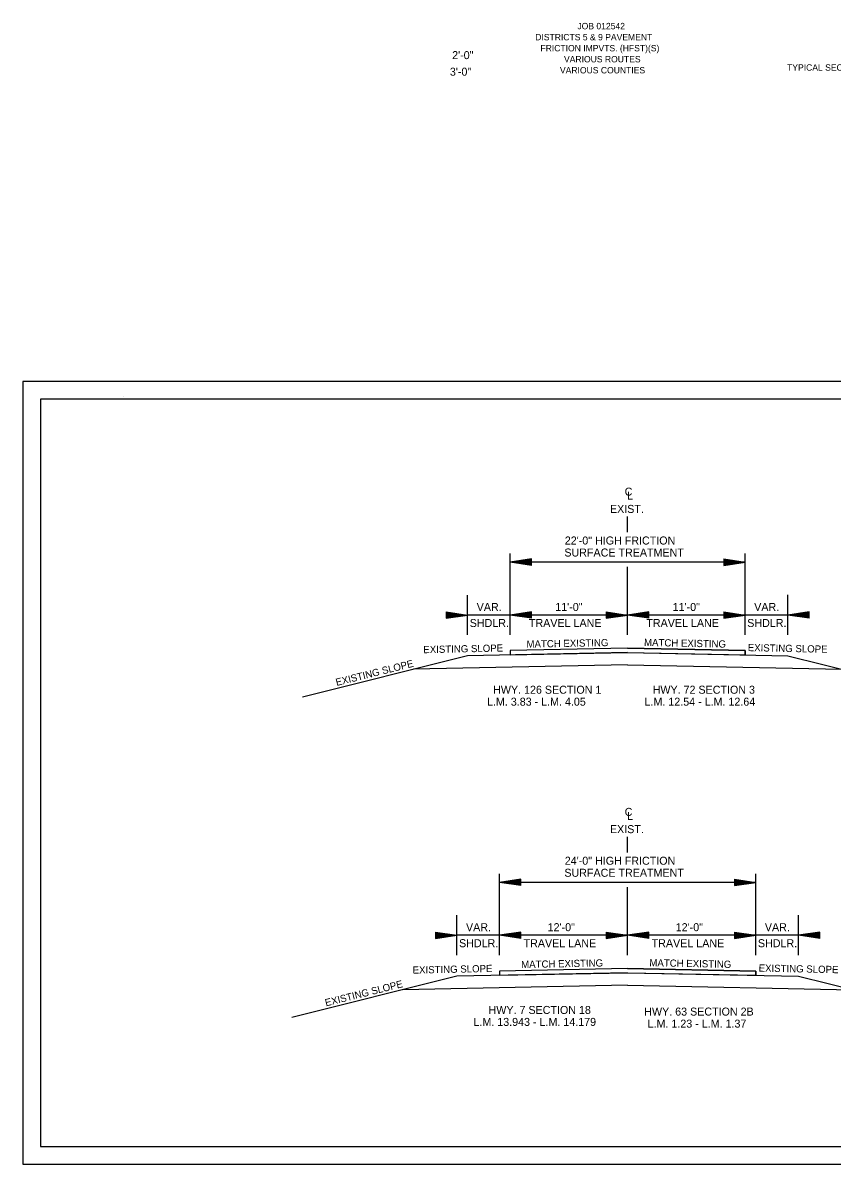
# Model space of a CAD drawing. Extents: x 34757 to 38214, y 51436 to 59430.
# Drawn here: x 34757 to 35894, y 55070 to 56673 of the extents above; entities that cross this region are included whole.
import ezdxf

# ---------------------------------------------------------------- set-up
doc = ezdxf.new("R2010")
doc.units = 0
for name, color, linetype in [('Default', 7, 'Continuous'), ('DSN_DRFT_Junk-No-Plot', 7, 'Continuous'), ('R_Border Notes', 7, 'Continuous'), ('R_Draft', 7, 'Continuous'), ('SHET_Border-Lines', 7, 'Continuous')]:
    doc.layers.add(name, color=color, linetype=linetype)

msp = doc.modelspace()

# ---------------------------------------------------------------- linework, layer by layer
at = {"layer": 'Default'}
for p, q in [((35606.6, 55957.6), (35606.6, 55979.7)), ((35441.6, 55813.4), (35441.6, 55927.7)), ((35771.6, 55813.4), (35771.6, 55927.7)), ((35471.6, 55920.1), (35441.6, 55915.6)), ((35771.6, 55915.6), (35441.6, 55915.6)), ((35471.6, 55911.1), (35441.6, 55915.6)), ((35471.6, 55919.4), (35446.6, 55915.6)), ((35471.6, 55911.9), (35446.6, 55915.6)), ((35471.6, 55918.6), (35451.8, 55915.6)), ((35471.6, 55912.6), (35451.8, 55915.6)), ((35471.6, 55917.8), (35456.8, 55915.6)), ((35471.6, 55913.4), (35456.8, 55915.6)), ((35471.6, 55917.1), (35461.9, 55915.6)), ((35471.6, 55914.1), (35461.9, 55915.6)), ((35471.6, 55916.3), (35466.9, 55915.6)), ((35471.6, 55914.9), (35466.9, 55915.6)), ((35471.6, 55911.1), (35471.6, 55920.1)), ((35741.6, 55920.1), (35771.6, 55915.6)), ((35741.6, 55920.1), (35741.6, 55911.1)), ((35741.6, 55919.4), (35766.6, 55915.6)), ((35741.6, 55918.6), (35761.5, 55915.6)), ((35741.6, 55917.8), (35756.5, 55915.6)), ((35741.6, 55917.1), (35751.4, 55915.6)), ((35741.6, 55916.3), (35746.4, 55915.6)), ((35741.6, 55911.1), (35771.6, 55915.6)), ((35741.6, 55914.1), (35751.4, 55915.6)), ((35741.6, 55912.6), (35761.5, 55915.6)), ((35741.6, 55911.9), (35766.6, 55915.6)), ((35741.6, 55913.4), (35756.5, 55915.6)), ((35741.6, 55914.9), (35746.4, 55915.6)), ((35606.6, 55813.4), (35606.6, 55908.8)), ((35381.6, 55813.4), (35381.6, 55869.3)), ((35831.6, 55813.7), (35831.6, 55869.6)), ((35351.6, 55845.8), (35381.6, 55841.3)), ((35351.6, 55845.8), (35351.6, 55836.8)), ((35351.6, 55845.1), (35376.6, 55841.3)), ((35351.6, 55844.3), (35371.5, 55841.3)), ((35351.6, 55843.6), (35366.5, 55841.3)), ((35351.6, 55842.8), (35361.4, 55841.3)), ((35351.6, 55842), (35356.4, 55841.3)), ((35351.6, 55836.8), (35381.6, 55841.3)), ((35351.6, 55839.9), (35361.4, 55841.3)), ((35351.6, 55838.4), (35371.5, 55841.3)), ((35351.6, 55837.6), (35376.6, 55841.3)), ((35351.6, 55839.1), (35366.5, 55841.3)), ((35351.6, 55840.6), (35356.4, 55841.3)), ((35441.6, 55841.3), (35381.6, 55841.3)), ((35471.6, 55845.8), (35441.6, 55841.3)), ((35606.6, 55841.3), (35441.6, 55841.3)), ((35471.6, 55836.8), (35441.6, 55841.3)), ((35471.6, 55845.1), (35446.6, 55841.3)), ((35471.6, 55837.6), (35446.6, 55841.3)), ((35471.6, 55844.3), (35451.8, 55841.3)), ((35471.6, 55838.4), (35451.8, 55841.3)), ((35471.6, 55843.6), (35456.8, 55841.3)), ((35471.6, 55839.1), (35456.8, 55841.3)), ((35471.6, 55842.8), (35461.9, 55841.3)), ((35471.6, 55839.9), (35461.9, 55841.3)), ((35471.6, 55842), (35466.9, 55841.3)), ((35471.6, 55840.6), (35466.9, 55841.3)), ((35471.6, 55836.8), (35471.6, 55845.8)), ((35576.6, 55845.8), (35606.6, 55841.3)), ((35576.6, 55845.8), (35576.6, 55836.8)), ((35576.6, 55845.1), (35601.6, 55841.3)), ((35576.6, 55844.3), (35596.5, 55841.3)), ((35576.6, 55843.6), (35591.5, 55841.3)), ((35576.6, 55842.8), (35586.4, 55841.3)), ((35576.6, 55842), (35581.4, 55841.3)), ((35576.6, 55836.8), (35606.6, 55841.3)), ((35576.6, 55839.9), (35586.4, 55841.3)), ((35576.6, 55838.4), (35596.5, 55841.3)), ((35576.6, 55837.6), (35601.6, 55841.3)), ((35576.6, 55839.1), (35591.5, 55841.3)), ((35576.6, 55840.6), (35581.4, 55841.3)), ((35636.6, 55845.8), (35606.6, 55841.3)), ((35771.6, 55841.3), (35606.6, 55841.3)), ((35636.6, 55836.8), (35606.6, 55841.3)), ((35636.6, 55845.1), (35611.6, 55841.3)), ((35636.6, 55837.6), (35611.6, 55841.3)), ((35636.6, 55844.3), (35616.8, 55841.3)), ((35636.6, 55838.4), (35616.8, 55841.3)), ((35636.6, 55843.6), (35621.8, 55841.3)), ((35636.6, 55839.1), (35621.8, 55841.3)), ((35636.6, 55842.8), (35626.9, 55841.3)), ((35636.6, 55839.9), (35626.9, 55841.3)), ((35636.6, 55842), (35631.9, 55841.3)), ((35636.6, 55840.6), (35631.9, 55841.3)), ((35636.6, 55836.8), (35636.6, 55845.8)), ((35741.6, 55845.8), (35771.6, 55841.3)), ((35741.6, 55845.8), (35741.6, 55836.8)), ((35741.6, 55845.1), (35766.6, 55841.3)), ((35741.6, 55844.3), (35761.5, 55841.3)), ((35741.6, 55843.6), (35756.5, 55841.3)), ((35741.6, 55842.8), (35751.4, 55841.3)), ((35741.6, 55842), (35746.4, 55841.3)), ((35741.6, 55836.8), (35771.6, 55841.3)), ((35741.6, 55839.9), (35751.4, 55841.3)), ((35741.6, 55838.4), (35761.5, 55841.3)), ((35741.6, 55837.6), (35766.6, 55841.3)), ((35741.6, 55839.1), (35756.5, 55841.3)), ((35741.6, 55840.6), (35746.4, 55841.3)), ((35831.6, 55841.3), (35771.6, 55841.3)), ((35861.6, 55845.8), (35831.6, 55841.3)), ((35861.6, 55836.8), (35831.6, 55841.3)), ((35861.6, 55845.1), (35836.6, 55841.3)), ((35861.6, 55837.6), (35836.6, 55841.3)), ((35861.6, 55844.3), (35841.8, 55841.3)), ((35861.6, 55838.4), (35841.8, 55841.3)), ((35861.6, 55843.6), (35846.8, 55841.3)), ((35861.6, 55839.1), (35846.8, 55841.3)), ((35861.6, 55842.8), (35851.9, 55841.3)), ((35861.6, 55839.9), (35851.9, 55841.3)), ((35861.6, 55842), (35856.9, 55841.3)), ((35861.6, 55840.6), (35856.9, 55841.3)), ((35861.6, 55836.8), (35861.6, 55845.8)), ((35606.6, 55813.4), (35606.6, 55821.3)), ((35381.6, 55784.1), (35149.6, 55726.1)), ((35606.6, 55788.6), (35381.6, 55784.1)), ((35606.6, 55794.6), (35441.6, 55791.3)), ((35441.6, 55791.3), (35441.6, 55785.3)), ((35606.6, 55794.6), (35771.6, 55791.3)), ((35606.6, 55788.6), (35831.6, 55784.1)), ((35771.6, 55791.3), (35771.6, 55785.3)), ((35831.6, 55784.1), (36063.6, 55726.1)), ((35606.6, 55771.1), (35305.5, 55765.1)), ((35606.6, 55771.1), (35907.7, 55765.1)), ((35606.6, 55507.6), (35606.6, 55529.7)), ((35426.6, 55363.4), (35426.6, 55477.7)), ((35456.6, 55470.1), (35426.6, 55465.6)), ((35786.6, 55465.6), (35426.6, 55465.6)), ((35456.6, 55461.1), (35426.6, 55465.6)), ((35456.6, 55469.4), (35431.6, 55465.6)), ((35456.6, 55461.9), (35431.6, 55465.6)), ((35456.6, 55468.6), (35436.8, 55465.6)), ((35456.6, 55462.6), (35436.8, 55465.6)), ((35456.6, 55467.8), (35441.8, 55465.6)), ((35456.6, 55463.4), (35441.8, 55465.6)), ((35456.6, 55467.1), (35446.9, 55465.6)), ((35456.6, 55464.1), (35446.9, 55465.6)), ((35456.6, 55466.3), (35451.9, 55465.6)), ((35456.6, 55464.9), (35451.9, 55465.6)), ((35456.6, 55461.1), (35456.6, 55470.1)), ((35756.6, 55470.1), (35786.6, 55465.6)), ((35756.6, 55470.1), (35756.6, 55461.1)), ((35756.6, 55469.4), (35781.6, 55465.6)), ((35756.6, 55468.6), (35776.5, 55465.6)), ((35756.6, 55467.8), (35771.5, 55465.6)), ((35756.6, 55467.1), (35766.4, 55465.6)), ((35756.6, 55466.3), (35761.4, 55465.6)), ((35756.6, 55461.1), (35786.6, 55465.6)), ((35756.6, 55464.1), (35766.4, 55465.6)), ((35756.6, 55462.6), (35776.5, 55465.6)), ((35756.6, 55461.9), (35781.6, 55465.6)), ((35756.6, 55463.4), (35771.5, 55465.6)), ((35756.6, 55464.9), (35761.4, 55465.6)), ((35786.6, 55363.4), (35786.6, 55477.7)), ((35606.6, 55363.4), (35606.6, 55458.8)), ((35366.6, 55363.4), (35366.6, 55419.3)), ((35846.6, 55363.4), (35846.6, 55419.3)), ((35336.6, 55395.8), (35366.6, 55391.3)), ((35336.6, 55395.8), (35336.6, 55386.8)), ((35336.6, 55395.1), (35361.6, 55391.3)), ((35336.6, 55394.3), (35356.5, 55391.3)), ((35336.6, 55393.6), (35351.5, 55391.3)), ((35336.6, 55392.8), (35346.4, 55391.3)), ((35336.6, 55392), (35341.4, 55391.3)), ((35336.6, 55386.8), (35366.6, 55391.3)), ((35336.6, 55389.9), (35346.4, 55391.3)), ((35336.6, 55388.4), (35356.5, 55391.3)), ((35336.6, 55387.6), (35361.6, 55391.3)), ((35336.6, 55389.1), (35351.5, 55391.3)), ((35336.6, 55390.6), (35341.4, 55391.3)), ((35426.6, 55391.3), (35366.6, 55391.3)), ((35456.6, 55395.8), (35426.6, 55391.3)), ((35606.6, 55391.3), (35426.6, 55391.3)), ((35456.6, 55386.8), (35426.6, 55391.3)), ((35456.6, 55395.1), (35431.6, 55391.3)), ((35456.6, 55387.6), (35431.6, 55391.3)), ((35456.6, 55394.3), (35436.8, 55391.3)), ((35456.6, 55388.4), (35436.8, 55391.3)), ((35456.6, 55393.6), (35441.8, 55391.3)), ((35456.6, 55389.1), (35441.8, 55391.3)), ((35456.6, 55392.8), (35446.9, 55391.3)), ((35456.6, 55389.9), (35446.9, 55391.3)), ((35456.6, 55392), (35451.9, 55391.3)), ((35456.6, 55390.6), (35451.9, 55391.3)), ((35456.6, 55386.8), (35456.6, 55395.8)), ((35576.6, 55395.8), (35606.6, 55391.3)), ((35576.6, 55395.8), (35576.6, 55386.8)), ((35576.6, 55395.1), (35601.6, 55391.3)), ((35576.6, 55394.3), (35596.5, 55391.3)), ((35576.6, 55393.6), (35591.5, 55391.3)), ((35576.6, 55392.8), (35586.4, 55391.3)), ((35576.6, 55392), (35581.4, 55391.3)), ((35576.6, 55386.8), (35606.6, 55391.3)), ((35576.6, 55389.9), (35586.4, 55391.3)), ((35576.6, 55388.4), (35596.5, 55391.3)), ((35576.6, 55387.6), (35601.6, 55391.3)), ((35576.6, 55389.1), (35591.5, 55391.3)), ((35576.6, 55390.6), (35581.4, 55391.3)), ((35636.6, 55395.8), (35606.6, 55391.3)), ((35786.6, 55391.3), (35606.6, 55391.3)), ((35636.6, 55386.8), (35606.6, 55391.3)), ((35636.6, 55395.1), (35611.6, 55391.3)), ((35636.6, 55387.6), (35611.6, 55391.3)), ((35636.6, 55394.3), (35616.8, 55391.3)), ((35636.6, 55388.4), (35616.8, 55391.3)), ((35636.6, 55393.6), (35621.8, 55391.3)), ((35636.6, 55389.1), (35621.8, 55391.3)), ((35636.6, 55392.8), (35626.9, 55391.3)), ((35636.6, 55389.9), (35626.9, 55391.3)), ((35636.6, 55392), (35631.9, 55391.3)), ((35636.6, 55390.6), (35631.9, 55391.3)), ((35636.6, 55386.8), (35636.6, 55395.8)), ((35756.6, 55395.8), (35786.6, 55391.3)), ((35756.6, 55395.8), (35756.6, 55386.8)), ((35756.6, 55395.1), (35781.6, 55391.3)), ((35756.6, 55394.3), (35776.5, 55391.3)), ((35756.6, 55393.6), (35771.5, 55391.3)), ((35756.6, 55392.8), (35766.4, 55391.3)), ((35756.6, 55392), (35761.4, 55391.3)), ((35756.6, 55386.8), (35786.6, 55391.3)), ((35756.6, 55389.9), (35766.4, 55391.3)), ((35756.6, 55388.4), (35776.5, 55391.3)), ((35756.6, 55387.6), (35781.6, 55391.3)), ((35756.6, 55389.1), (35771.5, 55391.3)), ((35756.6, 55390.6), (35761.4, 55391.3)), ((35846.6, 55391.3), (35786.6, 55391.3)), ((35876.6, 55395.8), (35846.6, 55391.3)), ((35876.6, 55386.8), (35846.6, 55391.3)), ((35876.6, 55395.1), (35851.6, 55391.3)), ((35876.6, 55387.6), (35851.6, 55391.3)), ((35876.6, 55394.3), (35856.8, 55391.3)), ((35876.6, 55388.4), (35856.8, 55391.3)), ((35876.6, 55393.6), (35861.8, 55391.3)), ((35876.6, 55389.1), (35861.8, 55391.3)), ((35876.6, 55392.8), (35866.9, 55391.3)), ((35876.6, 55389.9), (35866.9, 55391.3)), ((35876.6, 55392), (35871.9, 55391.3)), ((35876.6, 55390.6), (35871.9, 55391.3)), ((35876.6, 55386.8), (35876.6, 55395.8)), ((35606.6, 55338.6), (35366.6, 55333.8)), ((35606.6, 55344.6), (35426.6, 55341)), ((35426.6, 55341), (35426.6, 55335)), ((35606.6, 55344.6), (35786.6, 55341)), ((35606.6, 55338.6), (35846.6, 55333.8)), ((35786.6, 55341), (35786.6, 55335)), ((35366.6, 55333.8), (35134.6, 55275.8)), ((35606.6, 55321.1), (35290.5, 55314.8)), ((35606.6, 55321.1), (35922.7, 55314.8)), ((35846.6, 55333.8), (36078.6, 55275.8))]:
    msp.add_line(p, q, dxfattribs=at)
for points in [[(35441.6, 55791.3), (35441.6, 55785.3), (35606.6, 55788.6), (35771.6, 55785.3), (35771.6, 55791.3), (35606.6, 55794.6)], [(35426.6, 55341), (35426.6, 55335), (35606.6, 55338.6), (35786.6, 55335), (35786.6, 55341), (35606.6, 55344.6)]]:
    msp.add_lwpolyline(points, close=True, dxfattribs=at)
at = {"layer": 'DSN_DRFT_Junk-No-Plot'}
msp.add_lwpolyline([(34756.6, 56169.6), (34756.6, 55069.6), (36456.6, 55069.6), (36456.6, 56169.6)], close=True, dxfattribs=at)
at = {"layer": 'SHET_Border-Lines'}
msp.add_line((34897.7, 56148.2), (34897.7, 56148.2), dxfattribs=at)
msp.add_line((34897.7, 56148.2), (34897.7, 56148.2), dxfattribs=at)
for points in [[(34756.6, 55069.6), (36456.6, 55069.6), (36456.6, 56169.6), (34756.6, 56169.6)], [(34781.6, 55094.6), (36431.6, 55094.6), (36431.6, 56144.6), (34781.6, 56144.6)]]:
    msp.add_lwpolyline(points, close=True, dxfattribs=at)

# ---------------------------------------------------------------- texts
at = {"layer": 'Default'}
for s, height, p in [('2\'-0"', 11.25, (35360, 56622.5)), ('3\'-0"', 11.25, (35356.8, 56599.2)), ('C', 11.2, (35602.5, 56009.1)), ('L', 11.2, (35605.9, 56003.4)), ('EXIST.', 11.24, (35581.8, 55984.8)), ('22\'-0" HIGH FRICTION', 11.25, (35518.3, 55940.4)), ('SURFACE TREATMENT', 11.25, (35517.7, 55923.5)), ('VAR.', 11.25, (35394.5, 55847)), ('11\'-0"', 11.25, (35504.9, 55847)), ('11\'-0"', 11.25, (35669.9, 55847)), ('VAR.', 11.25, (35784.5, 55847)), ('SHDLR.', 11.25, (35384.7, 55824.5)), ('TRAVEL LANE', 11.25, (35467.9, 55824.5)), ('TRAVEL LANE', 11.25, (35632.9, 55824.5)), ('SHDLR.', 11.25, (35774.7, 55824.5)), ('HWY. 126 SECTION 1', 11.25, (35417.6, 55730.7)), ('HWY. 72 SECTION 3', 11.25, (35641.8, 55730.7)), ('L.M. 3.83 - L.M. 4.05', 11.25, (35409, 55713.9)), ('L.M. 12.54 - L.M. 12.64', 11.25, (35630.4, 55713.9)), ('C', 11.2, (35602.5, 55559.1)), ('L', 11.2, (35605.9, 55553.4)), ('EXIST.', 11.24, (35581.8, 55534.8)), ('24\'-0" HIGH FRICTION', 11.25, (35518.3, 55490.4)), ('SURFACE TREATMENT', 11.25, (35517.7, 55473.5)), ('VAR.', 11.25, (35379.5, 55397)), ('12\'-0"', 11.25, (35494.2, 55397)), ('12\'-0"', 11.25, (35674.2, 55397)), ('VAR.', 11.25, (35799.5, 55397)), ('SHDLR.', 11.25, (35369.7, 55374.5)), ('TRAVEL LANE', 11.25, (35460.4, 55374.5)), ('TRAVEL LANE', 11.25, (35640.4, 55374.5)), ('SHDLR.', 11.25, (35789.7, 55374.5)), ('HWY. 7 SECTION 18', 11.25, (35411.2, 55280.7)), ('HWY. 63 SECTION 2B', 11.25, (35630, 55278.4)), ('L.M. 13.943 - L.M. 14.179', 11.25, (35390, 55263.9)), ('L.M. 1.23 - L.M. 1.37', 11.25, (35634.7, 55261.5))]:
    msp.add_text(s, height=height, dxfattribs=at).set_placement(p)
for s, rotation, p in [('EXISTING SLOPE', 1.2244, (35319.6, 55787.6)), ('MATCH EXISTING', 1.146, (35464.6, 55795.3)), ('MATCH EXISTING', 358.7756, (35629.6, 55797.9)), ('EXISTING SLOPE', 358.7756, (35775.4, 55790.6)), ('EXISTING SLOPE', 14.0368, (35197.7, 55741.6)), ('MATCH EXISTING', 1.146, (35457.1, 55345.1)), ('MATCH EXISTING', 358.7756, (35637.1, 55347.8)), ('EXISTING SLOPE', 358.7756, (35790.7, 55340.3)), ('EXISTING SLOPE', 1.2244, (35304.6, 55337.3)), ('EXISTING SLOPE', 14.0368, (35182.7, 55291.3))]:
    msp.add_text(s, height=10.125, rotation=rotation, dxfattribs=at).set_placement(p)
at = {"layer": 'R_Border Notes'}
msp.add_text('TYPICAL SECTIONS OF IMPROVEMENT', height=9, dxfattribs=at).set_placement((35830.7, 56606.2))
at = {"layer": 'R_Draft'}
for s, p in [('JOB 012542', (35536, 56664.4)), ('DISTRICTS 5 & 9 PAVEMENT', (35476.8, 56648.9)), ('FRICTION IMPVTS. (HFST)(S)', (35484.1, 56633.4)), ('VARIOUS ROUTES', (35517.2, 56617.9)), ('VARIOUS COUNTIES', (35511.5, 56602.4))]:
    msp.add_text(s, height=9, dxfattribs=at).set_placement(p)

doc.saveas('drawing.dxf')
